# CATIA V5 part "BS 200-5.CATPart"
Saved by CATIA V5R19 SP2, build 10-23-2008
Part number: BS 200-5
Bounding box of the stored display mesh (mm): x -12.497 to 12.497, y -12.358 to 12.358, z 0 to 40
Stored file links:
  C:\Users\Bora\Desktop\3D Katı model\BS serisi\BS 200\BS 200-5.CATPart
  C:\Program Files\Dassault Systemes\B19\intel_a\reffiles\standard\MetricThickPitch.txt
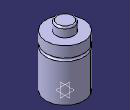
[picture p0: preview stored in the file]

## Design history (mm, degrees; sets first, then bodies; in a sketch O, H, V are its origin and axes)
Body1 (main body)
  Sketch1 on yz-plane, origin (0, 0, 0), H (0, 1, 0), V (0, 0, 1)
    point P1 (12.5, 27)
    point P4 (12.5, 25)
    point P5 (12.5, 27)
    point P6 (12.5, 25)
    point P7 (6, 39)
    point P9 (6, 39)
    line L1 (12.5, 27) -> (12.5, 34)
    line L2 (12.5, 0) -> (12.5, 25)
    arc A1 centre (12.5, 26) radius 1 from (12.5, 27) to (12.5, 25) ccw
    arc A2 centre (5, 39) radius 1 from (6, 39) to (5, 40) ccw
    line L3 (6, 39) -> (6, 34)
    line L4 (5, 40) -> (0, 40)
    point P11 (0, 40)
    line L5 (6, 34) -> (12.5, 34)
    line L6 (0, 0) -> (12.5, 0)
    coincidence: P11 V, P1 P5, P4 P6, P7 P9
    tangency: L4 A2
    horizontal: L5 H, L6 H
  Shaft1: profile Sketch1, axis Sketch1.V, angle 360
  Sketch2 on face of Shaft1 from Sketch1.L6, origin (0, 0, 0), H (1, 0, 0), V (0, -1, 0)
    point P1 (0, 0)
  Hole1: placed by Sketch2, at (0, 0, 0) direction (0, 0, 1), diameter 4.917, depth 4, threaded "M6", thread diameter 6, thread depth 4, pitch 1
